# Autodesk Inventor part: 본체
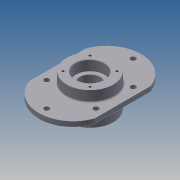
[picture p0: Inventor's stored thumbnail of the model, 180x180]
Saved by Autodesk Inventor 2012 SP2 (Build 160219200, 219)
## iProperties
Created: 2015-02
Part Number: 본체
Material: 알루미늄-6061
Document SubType Name: Modeling
Designer: Administrator
Density: 2.71 g/cm^3
Mass: 1637.13 g
Surface Area: 925.882 cm^2
Volume: 604.109 cm^3
Author: Administrator
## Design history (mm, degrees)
sketch "스케치1"
  geometry: C1 r 50 at (0, 0); 1 further point
  constraints: 1 centre point, 1 coincident
  dimensions: "d0" = 100 diameter of C1
extrude "돌출1" new body sketch "스케치1" distance "d1" = 35; taper "d2" = 0 deg
sketch "스케치2"
  geometry: L1 (-70, 60)-(-70, 0); L2 (70, 0)-(70, 60); L3 (70, 60)-(-70, 60); L4 (-70, 0)-(70, 0); C1 r 50 at (0, 0) reference; A1 r 74 centre (0, 36) between (70, 60) and (-70, 60); 1 further point
  constraints: 8 end point, 2 parallel, 2 point on circle, 1 centre point, 1 horizontal alignment, 1 midpoint, 1 perpendicular, 1 vertical, 1 vertical alignment
  dimensions: "d4" = 140 distance of L2.end L1.start; "d5" = 50 distance edge to line of A1 L3; "d7" = 60 distance of L2.start L2.end
extrude "돌출2" join sketch "스케치2" distance "d8" = 12; taper "d9" = 0 deg
sketch "스케치3"
  geometry: C1 r 50 at (0, 0); 1 further point
  constraints: 1 centre point, 1 coincident
  dimensions: "d10" = 100 diameter of C1
extrude "돌출3" join sketch "스케치3" distance "d11" = 23; taper "d12" = 0 deg
sketch "스케치5"
  geometry: L1 (0, 0)-(0, 41); L2 (0, 0)-(-28.991, 28.991); L3 (0, 0)-(-41, 0); C1 r 50 at (0, 0) reference; A1 r 41 centre (0, 0) between (-28.991, 28.991) and (0, 41)
  constraints: 6 end point, 3 point on circle, 1 centre point, 1 coincident, 1 perpendicular, 1 vertical
  dimensions: "d14" = 82 diameter of A1; "d15" = 45 deg angle of L2 L3
hole "구멍1" sketch "스케치5" at (-28.991, 28.991) diameter "d16" = 4.917; stored, may be unused: countersink angle "d20" = 90 deg, drill point angle "d22" = 118 deg; dims "d17" = 10, "d18" = 4, "d19" = 2, "d21" = 13
node "작업 평면1"
sketch "스케치6"
  geometry: C1 r 50 at (0, 0) reference; 1 further point
  constraints: 1 coincident
hole "구멍2" sketch "스케치6" at (0, 0) diameter "d27" = 45; stored, may be unused: countersink angle "d31" = 90 deg, drill point angle "d33" = 0 deg; dims "d28" = 10, "d29" = 62, "d30" = 22, "d32" = 48
sketch "스케치7"
  geometry: C1 r 22.5 at (0, 0) reference; 1 further point
  constraints: 1 coincident
hole "구멍3" sketch "스케치7" at (0, 0) diameter "d34" = 62; stored, may be unused: countersink angle "d38" = 90 deg, drill point angle "d40" = 0 deg; dims "d35" = 10, "d36" = 62, "d37" = 22, "d39" = 26
sketch "스케치8"
  geometry: L1 (-70, 60)-(-70, -60) reference; L2 (70, 60)-(70, -60) reference; L3 (-53, 56.976)-(-53, -56.976); L4 (53, -56.976)-(53, 56.976); C1 r 10 at (0, -93); A1 r 74 centre (0, -36) between (-70, -60) and (70, -60) reference; A2 r 74 centre (0, 36) between (70, 60) and (-70, 60) reference; A3 r 57 centre (0, -36) between (-53, -56.976) and (53, -56.976); A4 r 57 centre (0, 36) between (53, 56.976) and (-53, 56.976)
  constraints: 5 point on circle, 4 end point, 3 centre point, 3 other
  dimensions: "d41" = 17 radial gap between concentric circles of A4 A2; "d42" = 20 diameter of C1
extrude "돌출4" join sketch "스케치8" distance "d43" = 5; taper "d44" = 0 deg
sketch "스케치9"
  geometry: C1 r 10 at (0, 0) reference; C2 r 5.5 at (0, 0); 1 further point
  constraints: 1 centre point, 1 coincident
  dimensions: "d45" = 11 diameter of C2
extrude "돌출5" cut sketch "스케치9" stored distance "d46" = 5; taper "d47" = 0 deg
sketch "스케치12"
  geometry: C1 r 10 at (0, 93) reference; C2 r 50 at (0, 0) reference; 1 further point
  constraints: 1 vertical alignment, 1 other
  dimensions: "d56" = 65 distance of point (0, 65) C2.centre
feature "엠보싱1" sketch "스케치12" dims "d57" = 1, "d58" = 0
sketch "스케치13"
  geometry: L1 (-70, 60)-(-70, -60) reference; L2 (70, 60)-(70, -60) reference; L3 (-53, -56.976)-(-53, 56.976); L4 (53, 56.976)-(53, -56.976); C1 r 10 at (53, 39.976); A1 r 74 centre (0, -36) between (-70, -60) and (70, -60) reference; A2 r 74 centre (0, 36) between (70, 60) and (-70, 60) reference; A3 r 57 centre (0, -36) between (-53, -56.976) and (53, -56.976); A4 r 57 centre (0, 36) between (53, 56.976) and (-53, 56.976)
  constraints: 4 end point, 4 point on circle, 3 centre point, 1 point on line, 3 other
  dimensions: "d61" = 17 distance between parallel lines of L4 L2; "d62" = 20 diameter of C1; "d63" = 17 distance of C1.centre L4.start
extrude "돌출8" join sketch "스케치13" distance "d64" = 5; taper "d65" = 0 deg
sketch "스케치14"
  geometry: C1 r 10 at (0, 0) reference; 2 further points
  constraints: 1 coincident
hole "구멍4" sketch "스케치14" at (0, 0) diameter "d66" = 11; stored, may be unused: countersink angle "d70" = 90 deg, drill point angle "d72" = 0 deg; dims "d67" = 10, "d68" = 62, "d69" = 22, "d71" = 26
fillet "모깎기1" dims "d73" = 3
fillet "모깎기2" dims "d74" = 3
chamfer "모따기1" distance "d75" = 1; stored, may be unused: second distance "d76" = 2, angle "d77" = 45 deg
fillet "모깎기3" dims "d78" = 0.3
fillet "모깎기4" dims "d79" = 3
node "솔리드1"
mirror "대칭1"
pattern_circular "원형 패턴1" dims angle "d24" = 360 deg
mirror "대칭2"
mirror "대칭3"
mirror "대칭6"
mirror "대칭7"
other parameters: "d26" = -35
